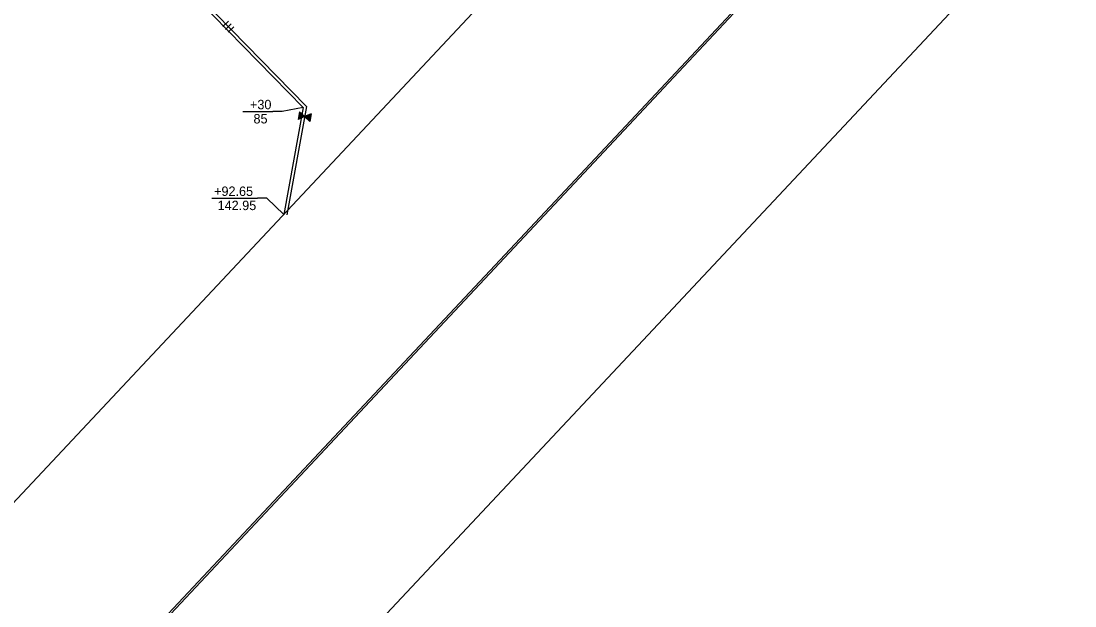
# Model space of a CAD drawing. Extents: x 979729 to 993523, y 1834148 to 1845433.
# Drawn here: x 991545 to 992215, y 1838663 to 1839035 of the extents above; entities that cross this region are included whole.
import ezdxf

# ---------------------------------------------------------------- set-up
doc = ezdxf.new("R2010")
doc.units = 0
for name, color, linetype in [('42', 7, 'Continuous'), ('51', 7, 'Continuous'), ('R_Draft', 7, 'Continuous'), ('S_EXIST_ROW', 7, 'Continuous')]:
    doc.layers.add(name, color=color, linetype=linetype)

msp = doc.modelspace()

# ---------------------------------------------------------------- linework, layer by layer
at = {"layer": '42'}
msp.add_lwpolyline([(991382.17, 1839394.42), (991468.64, 1839244.34), (991726.6, 1838980.6), (991714.1, 1838911.75)], dxfattribs=at)
at = {"layer": '51'}
for p, q in [((991676.99, 1839034.89), (991673.42, 1839031.39)), ((991678.74, 1839033.1), (991675.17, 1839029.61)), ((991680.49, 1839031.32), (991676.91, 1839027.82)), ((991723.01, 1838976.51), (991721.96, 1838976.06)), ((991722.8, 1838976.69), (991722.01, 1838976.35)), ((991722.62, 1838976.89), (991722.07, 1838976.65)), ((991722.41, 1838977.07), (991722.12, 1838976.94)), ((991722.24, 1838977.26), (991722.17, 1838977.24)), ((991722.19, 1838977.33), (991725.43, 1838974.2)), ((991725.43, 1838974.2), (991721.3, 1838972.41)), ((991725.35, 1838974.25), (991721.32, 1838972.51)), ((991725.11, 1838974.42), (991721.37, 1838972.8)), ((991724.96, 1838974.63), (991721.42, 1838973.1)), ((991724.75, 1838974.81), (991721.48, 1838973.39)), ((991724.57, 1838975.01), (991721.53, 1838973.69)), ((991724.33, 1838975.17), (991721.58, 1838973.98)), ((991724.18, 1838975.38), (991721.64, 1838974.28)), ((991723.94, 1838975.55), (991721.69, 1838974.58)), ((991723.77, 1838975.75), (991721.75, 1838974.87)), ((991723.4, 1838976.13), (991721.85, 1838975.46)), ((991723.23, 1838976.33), (991721.91, 1838975.76)), ((991723.52, 1838975.91), (991721.95, 1838975.23)), ((991729.57, 1838975.99), (991725.43, 1838974.2)), ((991725.43, 1838974.2), (991728.68, 1838971.07)), ((991725.53, 1838974.22), (991728.7, 1838971.17)), ((991725.82, 1838974.3), (991728.75, 1838971.46)), ((991726.03, 1838974.44), (991728.8, 1838971.76)), ((991726.29, 1838974.53), (991728.86, 1838972.06)), ((991726.53, 1838974.65), (991728.91, 1838972.35)), ((991726.81, 1838974.72), (991728.96, 1838972.65)), ((991727.02, 1838974.87), (991729.02, 1838972.94)), ((991727.31, 1838974.94), (991729.07, 1838973.24)), ((991727.54, 1838975.06), (991729.12, 1838973.53)), ((991727.83, 1838975.13), (991729.06, 1838973.94)), ((991728.02, 1838975.3), (991729.23, 1838974.12)), ((991728.25, 1838975.42), (991729.29, 1838974.42)), ((991728.51, 1838975.51), (991729.34, 1838974.72)), ((991728.78, 1838975.61), (991729.39, 1838975.01)), ((991729.01, 1838975.73), (991729.45, 1838975.31)), ((991729.27, 1838975.82), (991729.5, 1838975.6)), ((991729.51, 1838975.94), (991729.55, 1838975.9))]:
    msp.add_line(p, q, dxfattribs=at)
for points in [[(991381, 1839392.44), (991467.04, 1839243.12), (991724.44, 1838979.94), (991712.13, 1838912.1)], [(991678.7, 1839029.57), (991726.6, 1838980.6), (991714.1, 1838911.75)], [(991722.19, 1838977.33), (991721.3, 1838972.41)], [(991729.57, 1838975.99), (991728.68, 1838971.07)]]:
    msp.add_lwpolyline(points, dxfattribs=at)
at = {"layer": 'R_Draft'}
for p, q in [((991686.12, 1838977.39), (991705.18, 1838977.39)), ((991666.44, 1838922.34), (991695.42, 1838922.34))]:
    msp.add_line(p, q, dxfattribs=at)
for points in [[(991724.44, 1838979.94), (991711.18, 1838977.39), (991705.18, 1838977.39)], [(991712.13, 1838912.1), (991701.42, 1838922.34), (991695.42, 1838922.34)]]:
    msp.add_lwpolyline(points, dxfattribs=at)
at = {"layer": 'S_EXIST_ROW'}
for p, q in [((990293.19, 1837222.17), (993190.16, 1840310.88)), ((990366.13, 1837153.76), (993263.1, 1840242.47)), ((987322.66, 1834231.42), (992118.05, 1839344.95)), ((987410.19, 1834149.33), (992205.58, 1839262.87))]:
    msp.add_line(p, q, dxfattribs=at)

# ---------------------------------------------------------------- texts
at = {"layer": 'R_Draft'}
for s, p in [('+30', (991690.73, 1838978.89)), (' 85', (991690.73, 1838969.89)), ('+92.65', (991667.92, 1838923.84)), (' 142.95', (991667.92, 1838914.84))]:
    msp.add_text(s, height=6, rotation=360, dxfattribs=at).set_placement(p)

doc.saveas('drawing.dxf')
